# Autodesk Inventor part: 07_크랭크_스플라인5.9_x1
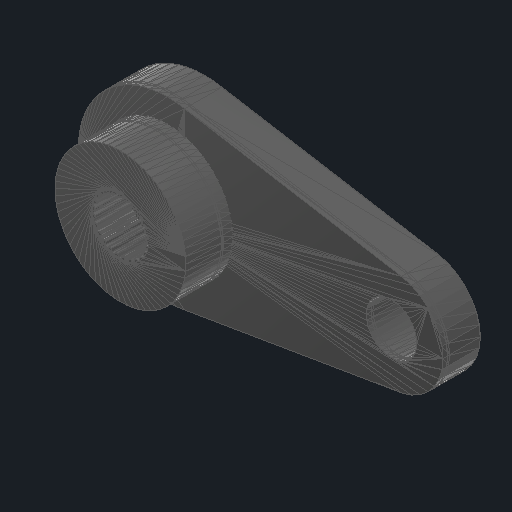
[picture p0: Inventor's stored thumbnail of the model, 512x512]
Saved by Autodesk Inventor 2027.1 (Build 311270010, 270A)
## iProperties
Created: 2026-11
Part Number: 07_크랭크_스플라인5.9_x1
Material: 일반
Document SubType Name: Modeling
Designer: djshs
Density: 1 g/cm^3
Appearance: 기본값
Author: djshs
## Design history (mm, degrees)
node "07_크랭크_스플라인5.9_x1"
  node "MeshFeature1"
